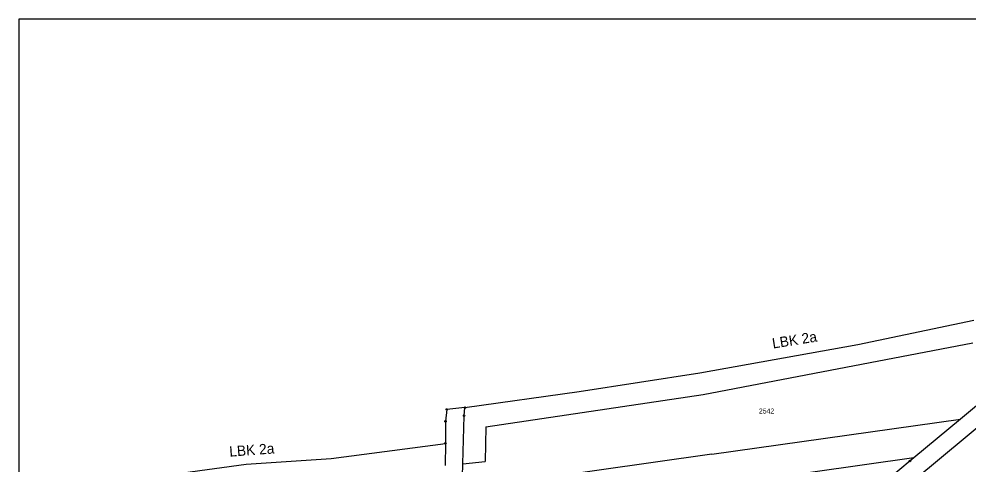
# Model space of a CAD drawing. Extents: x -565355 to -564154, y -1097649 to -1095548.
# Drawn here: x -565343 to -564697, y -1095851 to -1095548 of the extents above; entities that cross this region are included whole.
import ezdxf

# ---------------------------------------------------------------- set-up
doc = ezdxf.new("R2010")
doc.units = 0
for name, color, linetype in [('Vrstva 1', 7, 'Continuous'), ('Vrstva 13', 7, 'Continuous'), ('Vrstva 18', 7, 'Continuous'), ('Vrstva 24', 7, 'Continuous'), ('Vrstva 63', 7, 'Continuous')]:
    doc.layers.add(name, color=color, linetype=linetype)

msp = doc.modelspace()

# ---------------------------------------------------------------- linework, layer by layer
at = {"layer": 'Vrstva 1'}
for p, q in [((-564618.9, -1095750.13), (-564702.52, -1095819.63)), ((-564877.52, -1095802.97), (-564694, -1095767.75)), ((-564732.82, -1095859.97), (-564657.54, -1095797.49)), ((-565025.24, -1095824.91), (-564877.52, -1095802.97)), ((-565040.06, -1095817.34), (-565039.47, -1095811.86)), ((-565040.85, -1095849.94), (-565040.06, -1095817.34)), ((-564871.5, -1095843.46), (-564702.52, -1095819.63)), ((-564702.52, -1095819.63), (-564734.17, -1095845.93)), ((-565025.24, -1095824.91), (-565025.81, -1095848.33)), ((-565052.77, -1095836.13), (-565052.84, -1095851.27)), ((-564871.5, -1095843.46), (-565040.48, -1095867.29)), ((-564734.17, -1095845.93), (-564886.58, -1095867.42)), ((-564734.17, -1095845.93), (-564736.74, -1095848.07)), ((-565041.07, -1095858.74), (-565040.85, -1095849.94)), ((-565040.85, -1095849.94), (-565025.81, -1095848.33)), ((-564736.74, -1095848.07), (-564761.9, -1095868.94))]:
    msp.add_line(p, q, dxfattribs=at)
at = {"layer": 'Vrstva 13'}
for p, q in [((-564772.2, -1095768.91), (-564693.31, -1095752.31)), ((-564879.81, -1095788.15), (-564772.2, -1095768.91)), ((-564961.71, -1095800.8), (-564879.81, -1095788.15)), ((-565039.47, -1095811.86), (-564961.71, -1095800.8)), ((-565051.82, -1095813.09), (-565052.69, -1095821.13)), ((-565039.47, -1095811.86), (-565051.82, -1095813.09)), ((-565052.69, -1095821.13), (-565052.77, -1095836.13)), ((-565130.42, -1095846.37), (-565052.77, -1095836.13)), ((-565188.3, -1095850.34), (-565130.42, -1095846.37)), ((-565231.27, -1095856.19), (-565188.3, -1095850.34))]:
    msp.add_line(p, q, dxfattribs=at)
at = {"layer": 'Vrstva 24'}
for centre, radius in [((-565051.82, -1095813.09), 0.5), ((-565051.82, -1095813.09), 0.0327), ((-565039.47, -1095811.86), 0.5), ((-565039.47, -1095811.86), 0.0327), ((-565052.69, -1095821.13), 0.5), ((-565040.06, -1095817.34), 0.5), ((-565040.06, -1095817.34), 0.0327), ((-565052.69, -1095821.13), 0.0327), ((-565052.77, -1095836.13), 0.5), ((-565052.77, -1095836.13), 0.0327), ((-564736.74, -1095848.07), 0.5), ((-564736.74, -1095848.07), 0.0327)]:
    msp.add_circle(centre, radius, dxfattribs=at)
at = {"layer": 'Vrstva 63'}
for p, q in [((-565342.77, -1095547.8), (-565342.77, -1097647.8)), ((-564154.77, -1095547.8), (-565342.77, -1095547.8))]:
    msp.add_line(p, q, dxfattribs=at)

# ---------------------------------------------------------------- texts
at = {"layer": 'Vrstva 1'}
for rotation, p in [(9.08051, (-564829.94, -1095771.72)), (4.15955, (-565199.5, -1095845.17))]:
    msp.add_text('LBK 2a', height=7, rotation=rotation, dxfattribs=at).set_placement(p)
at = {"layer": 'Vrstva 18'}
msp.add_text('2542', height=3.4, dxfattribs=at).set_placement((-564839.57, -1095815.85))

doc.saveas('drawing.dxf')
